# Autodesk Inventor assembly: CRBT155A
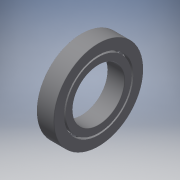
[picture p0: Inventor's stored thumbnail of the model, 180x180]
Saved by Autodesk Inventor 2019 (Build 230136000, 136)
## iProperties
Category: PARTsolutions
Company: IKO
Created: 2023-09
Part Number: CRBT155A
Catalog Web Link: www.cadenas.de
Description: Ultra Slim Type Crossed Roller Bearings (CRBT...A)-
Vendor: IKO
Document SubType Name: Assembly
Designer: psAdmin
Manufacturer: IKO
Mass: 1.59961 g
Surface Area: 24.8189 cm^2
Volume: 1.59961 cm^3
Density: 1 g/cm^3
Title: CRBT155A
Author: Cadenas PARTsolutions
PSOL_IDENT_0: {$CADENAS_DATA/23d-libs/iko/iko_bearings/crossed_rb/ultra_slim_type_crb/ultra_slim_type_crbt.prj},20
PSOL_IDENT_1: 1 {VTYP=3D},{NB=CRBT155A},{LINA=CRBT155A},{NN=Ultra Slim Type Crossed Roller Bearings (CRBT...A)},{D
PSOL_IDENT_2: ATE=09.07.2020 23:28:49},{GEOMDATE=08.07.2020 06:24:28},{VERSION=},{LINEID=220},{WBVAR=},{WBNUMERIC=
PSOL_IDENT_3: }  {NB=CRBT155A},{LINA=CRBT155A},{KT=DUMMY},{IDNR=},{STDRT=15},{ORDER=CRBT155A},{MASS=11.9},{SD=15},
PSOL_IDENT_4: {D=26},{B=5},{SR=0.15},{SDA=17.5},{DA=22.0},{DAR=2.0},{ZEFF=16},{RS=0.3},{DETC=1.6},{PCDRL=19.6},{SD
PSOL_IDENT_5: OR=20.10},{DIRR=19.10},{COG=0.0},{SDOG=0.0},{OH=0.0},{NH=0},{CR=1320},{COR=1110},{SC=0},{N=8},{N1=1.
PSOL_IDENT_6: 67}
NB: CRBT155A
NN: Ultra Slim Type Crossed Roller Bearings (CRBT...A)
NBSYN: $ORDER.
LINA: CRBT155A
CATALOG: IKO (Nippon Thompson
STDRT: 15
ORDER: CRBT155A
MASS: 11.9
SD: 15
D: 26
B: 5
SR: 0.15
SDA: 17.5
DA: 22
CR: 1320
COR: 1110
SUPPLIER: IKO
ARTICLENO: CRBT155A
BOMINFO: CRBT155A
CREATOR: CADENAS GmbH
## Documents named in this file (7)
- e:\temp\worker_COMMON_2\temp\tmp_6716_2_PHiGY\format_0\CRBT155A.iam
- e:\temp\worker_COMMON_2\temp\tmp_6716_2_PHiGY\format_0\CRBT155A_PART1.ipt
- e:\temp\worker_COMMON_2\temp\tmp_6716_2_PHiGY\format_0\CRBT155A_PART2.ipt
- e:\temp\worker_COMMON_2\temp\tmp_6716_2_PHiGY\format_0\CRBT155A_PART3.ipt
- e:\temp\worker_COMMON_2\temp\tmp_6716_2_PHiGY\format_0\CRBT155A_PART4.ipt
- e:\temp\worker_COMMON_2\temp\tmp_6716_2_PHiGY\format_0\CRBT155A_PART5.ipt
- e:\temp\worker_COMMON_2\temp\tmp_6716_2_PHiGY\format_0\CRBT155A_PART6.ipt
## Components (34 placed, 6 different names)
1. CRBT155A_PART1:1
2. CRBT155A_PART2:1
3. CRBT155A_PART3:1
4. CRBT155A_PART3:2
5. CRBT155A_PART3:3
6. CRBT155A_PART3:4
7. CRBT155A_PART3:5
8. CRBT155A_PART3:6
9. CRBT155A_PART3:7
10. CRBT155A_PART3:8
11. CRBT155A_PART4:1
12. CRBT155A_PART4:2
13. CRBT155A_PART4:3
14. CRBT155A_PART4:4
15. CRBT155A_PART4:5
16. CRBT155A_PART4:6
17. CRBT155A_PART4:7
18. CRBT155A_PART4:8
19. CRBT155A_PART5:1
20. CRBT155A_PART5:2
21. CRBT155A_PART5:3
22. CRBT155A_PART5:4
23. CRBT155A_PART5:5
24. CRBT155A_PART5:6
25. CRBT155A_PART5:7
26. CRBT155A_PART5:8
27. CRBT155A_PART6:1
28. CRBT155A_PART6:2
29. CRBT155A_PART6:3
30. CRBT155A_PART6:4
31. CRBT155A_PART6:5
32. CRBT155A_PART6:6
33. CRBT155A_PART6:7
34. CRBT155A_PART6:8
